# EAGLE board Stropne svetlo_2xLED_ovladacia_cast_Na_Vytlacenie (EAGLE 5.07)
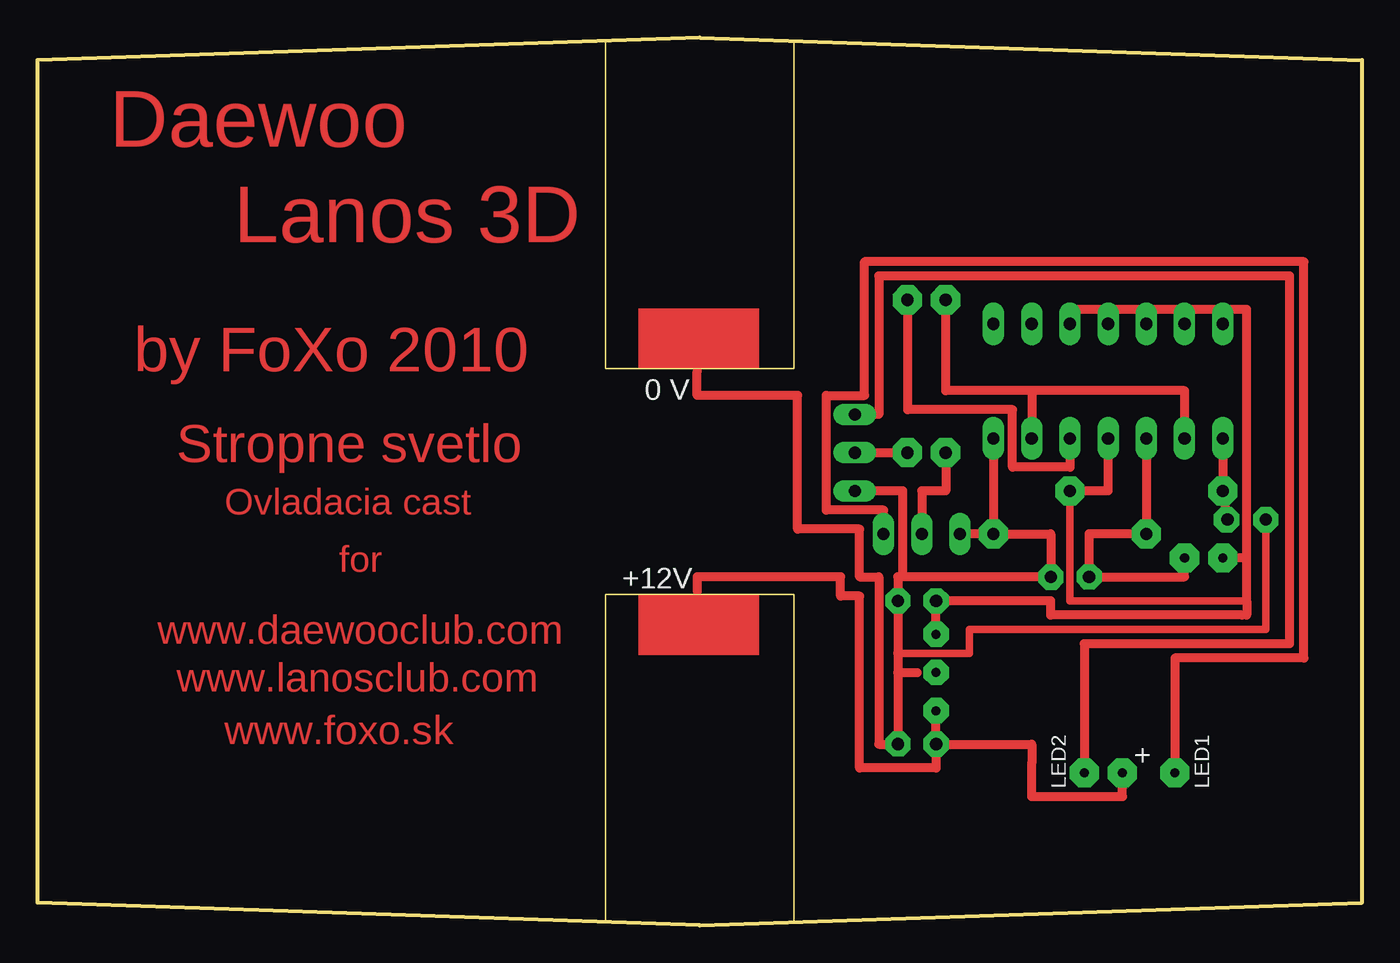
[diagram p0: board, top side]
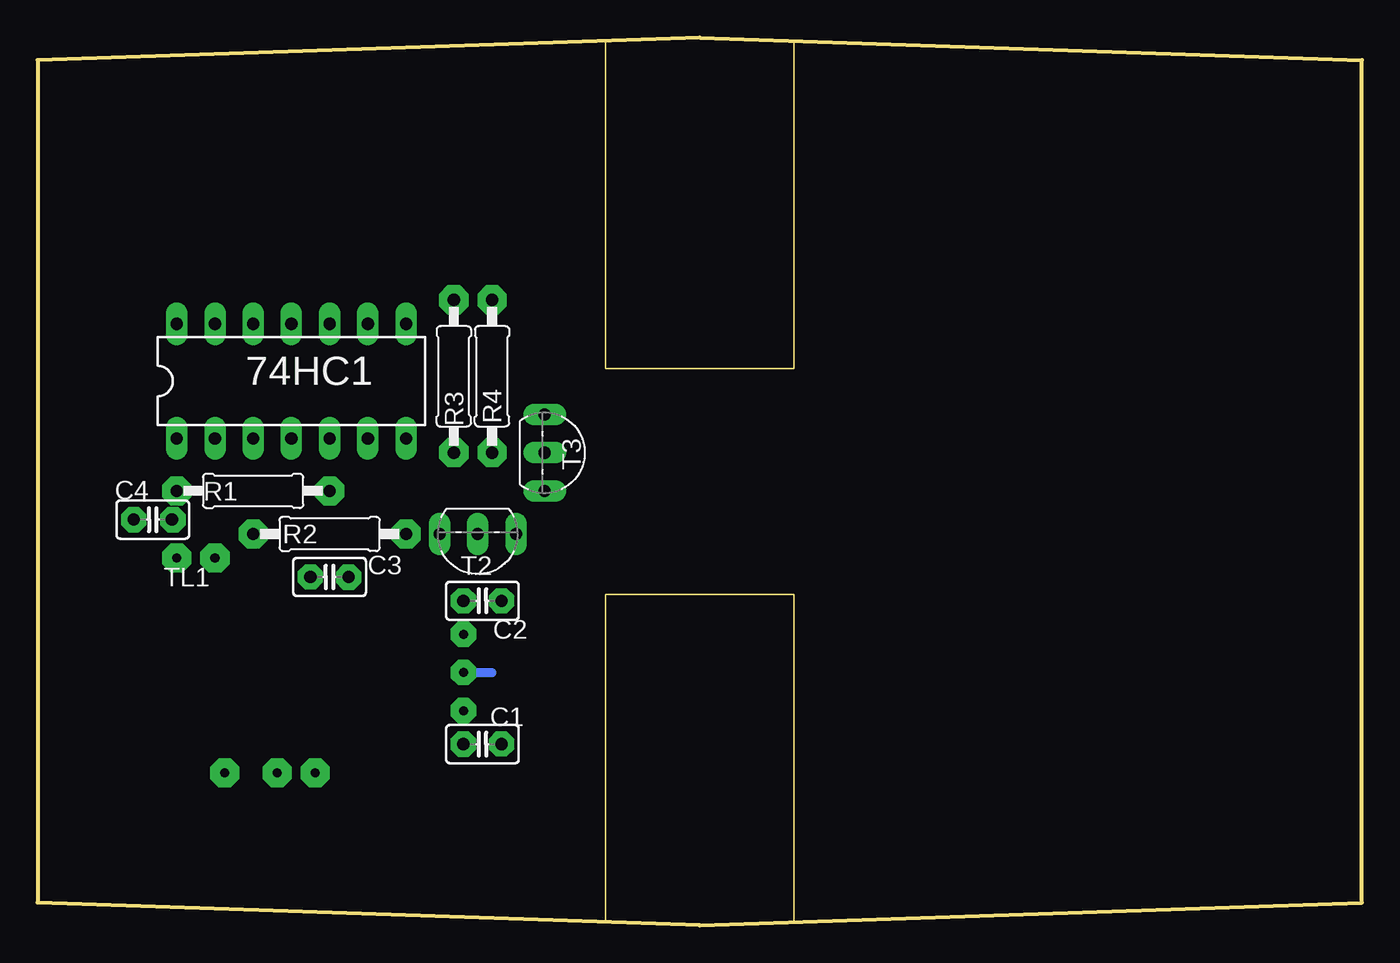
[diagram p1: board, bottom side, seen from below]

Size 88 x 59 mm. Coordinates in mm from the lower left corner, seen from the top.
Outline: 37.73,58.75 37.73,37 50.27,37 50.27,58.75
Outline: 37.73,0.25 37.73,22 50.27,22 50.27,0.25
Outline: 88,57.5 88,1.5 44,0 0,1.5 0,57.5 44,59 88,57.5
Copper layers (1*16): Top 0.035mm / dielectric 1.5mm / Bottom 0.035mm
Design rules "default *": minimum track width 10mil, minimum drill 24mil, track to track 8mil, track to pad 8mil, pad to pad 8mil, via to via 8mil, smd to smd 8mil, copper to edge 40mil, drill to drill 8mil, minimum pad ring 12mil, minimum via ring 8mil, stop-mask expansion 4mil, vias tented up to drill 0mil, thermal gap 10mil

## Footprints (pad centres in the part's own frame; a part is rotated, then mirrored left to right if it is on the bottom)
DIL14 = drill 0.813 long: 1 -7.62,-3.81; 2 -5.08,-3.81; 3 -2.54,-3.81; 4 0,-3.81; 5 2.54,-3.81; 6 5.08,-3.81; 7 7.62,-3.81; 8 7.62,3.81; 9 5.08,3.81; 10 2.54,3.81; 11 0,3.81; 12 -2.54,3.81; 13 -5.08,3.81; 14 -7.62,3.81
C025-025X050 = drill 0.813 octagon: 1 -1.27,0; 2 1.27,0
R-10 = drill 0.813 pad 1.93 octagon: 1 -5.08,0; 2 5.08,0
TO92-CBE = drill 0.813 long: B 0,0; C -2.54,0; E 2.54,0

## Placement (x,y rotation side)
74HC1  [DIL14]  71.14,36.17 0 bottom
C1  [C025-025X050]  58.44,12.04 0 bottom
C2  [C025-025X050]  58.44,21.57 0 bottom
C3  [C025-025X050]  68.6,23.16 180 bottom
C4  [C025-025X050]  80.34,26.96 180 bottom
R1  [R-10]  73.68,28.87 180 bottom
R2  [R-10]  68.6,26.01 0 bottom
R3  [R-10]  60.34,36.49 270 bottom
R4  [R-10]  57.8,36.49 270 bottom
T2  [TO92-CBE]  58.76,26.01 180 bottom
T3  [TO92-CBE]  54.31,31.41 270 bottom

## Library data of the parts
74HC1 = 74ac-logic
C1-C4 = rcl
R1-R4 = #PaJa_21
T2 T3 = transistor

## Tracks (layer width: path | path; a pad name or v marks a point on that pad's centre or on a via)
S$1
  Top 0.61: 59.71,11.41 59.71,10.46 54.63,10.46 54.63,21.88 53.36,21.88 53.36,23.16 43.83,23.16 43.83,22.2
S$2
  Top 0.61: 55.26,28.87 57.48,28.87 57.48,23.16 | 57.17,22.2 57.17,23.16 57.48,23.16 | 66.69,23.16 57.48,23.16
S$3  (via drill 0.6 pad 1.68)
  other vias: 59.71,16.8
S$5  (via drill 0.6 pad 1.68)
  other vias: 57.81,41.58
S$6  (via drill 0.6 pad 1.68)
  other vias: 79.02,26.95
S$7  (via drill 0.6 pad 1.68)
  other vias: 73.69,26.02
S$8  (via drill 0.6 pad 1.68)
  other vias: 67.34,23.14
S$9  (via drill 0.6 pad 1.68)
  other vias: 68.59,28.88
S$11  (via drill 0.6 pad 1.68)
  other vias: 78.78,28.88
S$12  (via drill 0.6 pad 1.68)
  other vias: 81.61,26.95
S$13  (via drill 0.6 pad 1.68)
  other vias: 57.18,21.56
S$14  (via drill 0.6 pad 1.68)
  other vias: 63.53,26.01
S$15  (via drill 0.6 pad 1.68)
  other vias: 57.18,12.05
S$16  (via drill 0.6 pad 1.68)
  other vias: 59.71,19.34
S$17  (via drill 0.6 pad 1.68)
  other vias: 59.7,21.56
S$18  (via drill 0.6 pad 1.68)
  other vias: 59.7,12.04
S$19  (via drill 0.6 pad 1.68)
  other vias: 60.36,31.39
S$20  (via drill 0.6 pad 1.68)
  other vias: 57.8,31.4
S$21  (via drill 0.6 pad 1.68)
  other vias: 60.34,41.58
S$22  (via drill 0.6 pad 1.68)
  other vias: 69.89,23.16
S$23  (via drill 0.6 pad 1.68)
  other vias: 59.71,14.27
S$24
  Bottom 0.61: 59.07,16.8 57.8,16.8
S$55  (via drill 0.6 pad 1.93)
  other vias: 78.76,24.43
S$56  (via drill 0.6 pad 1.93)
  other vias: 69.55,10.14
S$57  (via drill 0.6 pad 1.93)
  other vias: 75.58,10.14
S$60  (via drill 0.6 pad 1.93)
  other vias: 76.22,24.43
S$61  (via drill 0.6 pad 1.93)
  other vias: 72.09,10.14
S$62
  Top 0.61: 78.76,31.09 78.76,29.51
S$63
  Top 0.61: 69.23,28.87 71.14,28.87 71.14,31.09
S$64
  Top 0.61: 73.68,31.09 73.68,26.65
S$65
  Top 0.61: 63.52,31.09 63.52,26.65
S$66
  Top 0.61: 64.15,26.01 67.33,26.01 67.33,23.79
S$67
  Top 0.61: 73.04,26.01 69.87,26.01 69.87,23.79
S$68
  Top 0.61: 70.5,23.16 76.22,23.16 76.22,23.79
S$69
  Top 0.61: 59.71,12.68 59.71,13.63
S$70
  Top 0.5: 68.6,28.23 68.6,21.57 80.34,21.57
  Top 0.61: 68.6,40.94 80.34,40.94 80.34,24.43 | 80.34,24.43 79.39,24.43 | 80.34,20.61 80.34,21.57 80.34,24.43
S$71
  Top 0.61: 78.76,28.23 78.98,27.63
S$72
  Top 0.5: 57.17,18.07 61.93,18.07 61.93,19.66 81.61,19.66 81.61,26.33
  Top 0.61: 57.17,16.8 57.17,12.68 | 57.17,16.8 58.44,16.8 | 57.17,16.8 57.17,18.07 57.17,20.93
S$73
  Top 0.61: 59.71,19.98 59.71,20.93
S$74
  Top 0.61: 80.03,20.61 67.33,20.61 67.33,21.57 60.34,21.57
S$76
  Top 0.61: 60.34,12.04 66.06,12.04 66.06,10.77
S$77
  Top 0.61: 66.06,10.77 66.06,8.55 72.09,8.55 72.09,9.18
S$78
  Top 0.61: 60.34,40.94 60.34,35.54 66.06,35.54 | 76.22,33.63 76.22,35.54 66.06,35.54 | 66.06,35.54 66.06,33.63
S$79
  Top 0.61: 57.8,40.94 57.8,34.27 64.79,34.27 64.79,30.46 68.6,30.46 68.6,31.09
S$80
  Top 0.61: 62.88,26.01 61.93,26.01
S$81
  Top 0.61: 60.34,30.77 60.34,28.87 58.76,28.87 58.76,26.96
S$82
  Top 0.61: 55.26,31.41 57.17,31.41
S$83
  Top 0.61: 43.83,36.81 43.83,35.22 50.5,35.22 50.5,26.33 54.63,26.33 54.63,23.16 55.9,23.16 55.9,12.04 56.53,12.04
S$84
  Top 0.61: 69.55,10.77 69.55,18.71 83.2,18.71 83.2,43.16 55.9,43.16 55.9,33.95 55.26,33.95
S$85
  Top 0.61: 56.22,27.28 56.22,27.6 52.4,27.6 52.4,35.22 54.94,35.22 54.94,44.11 84.15,44.11 84.15,17.76 75.58,17.76 75.58,10.77
(copper drawn outside any net)
  shapes: Top area x2

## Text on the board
Top: Daewoo | Lanos 3D | by FoXo 2010 | Stropne svetlo | Ovladacia cast | for | www.daewooclub.com | www.lanosclub.com | www.foxo.sk
tNames: 0 V | +12V | LED2 | + | LED1
bNames: TL1
Doplnky: E | B | C | C | B | E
